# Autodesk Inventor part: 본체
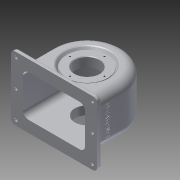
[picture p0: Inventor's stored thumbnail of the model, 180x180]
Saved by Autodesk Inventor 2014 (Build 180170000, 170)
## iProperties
Created: 2015-09
Part Number: 본체
Material: 알루미늄 6061
Document SubType Name: Modeling
Designer: SEC
Density: 2.71 g/cm^3
Appearance: 알루미늄 - 평지
Mass: 767.564 g
Surface Area: 941.03 cm^2
Volume: 283.234 cm^3
Author: SEC
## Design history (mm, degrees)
sketch "스케치1"
  geometry: L1 (-57, 0)-(-57, -47); L2 (57, 0)-(57, -47); L3 (57, -47)-(-57, -47); A1 r 57 centre (0, 0) between (57, 0) and (-57, 0); 1 further point
  constraints: 6 end point, 2 point on circle, 2 tangent, 1 centre point, 1 coincident, 1 parallel, 1 perpendicular, 1 vertical
  dimensions: "d1" = 47 distance from line of point (0, 0) L3; "d2" = 57 radius of A1
extrude "돌출1" new body sketch "스케치1" distance "d3" = 77; taper "d4" = 0 deg
sketch "스케치4"
  geometry: L1 (57, 77)-(57, 0) reference; L2 (57, 0)-(-47, 0) reference; L3 (-47, 77)-(57, 77) reference; L4 (-47, 0)-(-47, 77) reference; L5 (33, 73.111)-(33, 74); L6 (33, 74)-(20, 74); L7 (20, 74)-(20, 58); L8 (20, 58)-(28, 58); L9 (28, 58)-(39.747, 72); L10 (39.747, 72)-(51, 72); L11 (51, 72)-(51, 5); L12 (51, 5)-(20, 5); L13 (20, 5)-(20, 0); L14 (0, 0)-(0, 77); L15 (37.416, 77)-(0, 77); L16 (37.416, 77)-(33.883, 72.79); A1 r 0.5 centre (33.5, 73.111) between (33, 73.111) and (33.883, 72.79); 1 further point
  constraints: 24 end point, 7 perpendicular, 5 point on line, 2 parallel, 2 point on circle, 2 tangent, 1 centre point, 1 collinear
  dimensions: "d18" = 66 diameter of L5 L14; "d19" = 40 diameter of L7 L14; "d20" = 3 distance between parallel lines of L3 L6; "d21" = 50 deg angle of L8 L9; "d22" = 56 diameter of L8.end L14; "d23" = 16 distance between parallel lines of L8 L6; "d24" = 5 distance between parallel lines of L16 L9; "d25" = 6 distance between parallel lines of L11 L1; "d26" = 5 distance between parallel lines of L3 L10; "d27" = 5 distance between parallel lines of L12 L2; "d28" = 40 diameter of L13 L14; "d134" = 0.5 radius of A1
  node "절단 모서리 투영1"
sketch "스케치5"
  geometry: L1 (57, -47)-(-57, -47) reference; C1 r 31 at (0, 0)
  constraints: 1 centre point
  dimensions: "d29" = 62 diameter of C1; "d30" = 47 distance from line of C1.centre L1
extrude "돌출4" join sketch "스케치5" distance "d31" = 10; taper "d32" = 0 deg
sketch "스케치6"
  geometry: C1 r 31 at (0, 0) reference; C2 r 20 at (0, 0)
  constraints: 1 centre point, 1 coincident
  dimensions: "d34" = 40 diameter of C2
extrude "돌출5" cut sketch "스케치6" distance "d35" = 10; taper "d36" = 0 deg
sketch "스케치7"
  geometry: L1 (-13, 90.5)-(127, 90.5); L2 (127, 90.5)-(127, -13.5); L3 (127, -13.5)-(-13, -13.5); L4 (-13, -13.5)-(-13, 90.5); L5 (0, 0)-(0, 77) reference; L6 (0, 77)-(114, 77) reference; L7 (114, 77)-(114, 0) reference; L8 (114, 0)-(0, 0) reference; L9 (114, 38.5)-(80.915, 38.5); 1 further point
  constraints: 10 end point, 3 parallel, 1 horizontal, 1 midpoint, 1 perpendicular
  dimensions: "d37" = 140 distance of L1.start L1.end; "d38" = 104 distance of L1.end L2.end; "d39" = 70 distance from line of point (57, 0) L2; "d40" = 52 distance between parallel lines of L9 L1
extrude "돌출6" join sketch "스케치7" distance "d41" = 7; taper "d42" = 0 deg
revolve "회전2" stored, may be unused: angle "d43" = 90 deg
node "작업 평면1"
sketch "스케치14"
  geometry: L1 (29, 58)-(85, 58) reference; L2 (29, 58)-(17.253, 72) reference; L3 (85, 58)-(96.747, 72) reference; L4 (108, 72)-(108, 5) reference; L5 (6, 72)-(6, 5) reference; L6 (6, 5)-(108, 5) reference; L7 (6, 72)-(108, 72) reference; 1 further point
extrude "돌출10" cut sketch "스케치14" distance "d64" = 80; taper "d65" = 0 deg
sketch "스케치15"
  geometry: L1 (17.253, 72)-(29, 58) reference; L2 (29, 58)-(85, 58) reference; L3 (85, 58)-(96.747, 72) reference; L4 (127, -13.5)-(127, 90.5) reference; L5 (17.253, 72)-(96.747, 72); 1 further point
  constraints: 2 end point, 1 perpendicular, 1 point on line
extrude "돌출11" cut sketch "스케치15" distance "d67" = 15.5; taper "d68" = 0 deg
sketch "스케치18"
  geometry: L1 (-13, -90.5)-(127, -90.5) reference; L2 (-13, 13.5)-(-13, -90.5) reference; C1 r 2.5 at (-5, -82.5); C2 r 2.5 at (-5, -38.5); C3 r 2.5 at (-5, 5.5); 1 further point
  constraints: 3 centre point
  dimensions: "d69" = 5 diameter of C1; "d70" = 8 distance from line of C1.centre L1; "d71" = 8 distance from line of C1.centre L2; "d72" = 5 diameter of C2; "d73" = 5 diameter of C3; "d74" = 8 distance from line of C2.centre L2; "d75" = 8 distance from line of C3.centre L2; "d76" = 44 distance of C1.centre C2.centre; "d77" = 44 distance of C3.centre C2.centre
extrude "돌출12" cut sketch "스케치18" distance "d78" = 15.5; taper "d79" = 0 deg
node "작업 평면3"
sketch "스케치19"
  geometry: L1 (57, 0)-(57, 77) reference; L2 (57, 77)-(-57, 77) reference; C1 r 6 at (0, 38.5); 1 further point
  constraints: 1 centre point
  dimensions: "d81" = 12 diameter of C1; "d82" = 57 distance from line of C1.centre L1; "d83" = 38.5 distance from line of C1.centre L2
extrude "돌출13" join sketch "스케치19" stored distance "d84" = 15.5; taper "d85" = 10 deg
sketch "스케치20"
  geometry: C1 r 6 at (0, 0) reference; 1 further point
hole "구멍1" sketch "스케치20" at (0, 0) diameter "d86" = 4.459; stored, may be unused: countersink angle "d90" = 90 deg, drill point angle "d92" = 118 deg; dims "d87" = 20, "d88" = 4, "d89" = 2, "d91" = 25
sketch "스케치21"
  geometry: L1 (0, 57)-(0, 0) reference; L2 (90.5, -54)-(-13.5, -54) reference; 1 further point
  constraints: 1 other
  dimensions: "d93" = 38.5 distance from line of point (38.5, -24) L1; "d94" = 30 distance from line of point (38.5, -24) L2
feature "엠보싱1" sketch "스케치21" dims "d1" = 47, "d2" = 57, "d95" = 0.5, "d96" = 0
sketch "스케치22" dims "d97" = 56
  geometry: L1 (0, 0)-(0, 28); C1 r 20 at (0, 0) reference
  constraints: 2 end point, 1 coincident, 1 vertical, 1 vertical alignment, 2 other
hole "구멍2" sketch "스케치22" at (0, 28) diameter "d98" = 2.459; stored, may be unused: countersink angle "d102" = 90 deg, drill point angle "d104" = 118 deg; dims "d99" = 7, "d100" = 4, "d101" = 2, "d103" = 9
sketch "스케치23" dims "d108" = 48
  geometry: L1 (0, 0)-(0, 24); C1 r 31 at (0, 0) reference
  constraints: 2 end point, 1 coincident, 1 vertical, 1 vertical alignment, 2 other
hole "구멍3" sketch "스케치23" at (0, 24) diameter "d109" = 2.459; stored, may be unused: countersink angle "d113" = 90 deg, drill point angle "d115" = 118 deg; dims "d110" = 6, "d111" = 4, "d112" = 2, "d114" = 8
fillet "모깎기1" dims "d119" = 3
fillet "모깎기2" dims "d120" = 14
sketch "스케치24"
  geometry: L1 (6, 72)-(108, 72) reference; L2 (108, 72)-(108, 5) reference; L3 (108, 5)-(6, 5) reference; L4 (6.483, 72)-(6.483, 5) reference; L5 (107.517, 5)-(107.517, 72) reference; 1 further point
extrude "돌출14" join sketch "스케치24" distance "d121" = 60; taper "d122" = 0 deg
sketch "스케치25"
  geometry: L1 (6, 72)-(107.517, 72) reference; L2 (107.517, 5)-(6, 5) reference; L3 (6, 5)-(6, 72) reference; L4 (6.483, 72)-(6.483, 5) reference; 1 further point
extrude "돌출15" join sketch "스케치25" distance "d123" = 60; taper "d124" = 0 deg
fillet "모깎기3" dims "d125" = 9
fillet "모깎기4" dims "d126" = 9
fillet "모깎기5" dims "d127" = 9
fillet "모깎기6" dims "d128" = 7
fillet "모깎기7" dims "d129" = 3
chamfer "모따기1" distance "d130" = 1; stored, may be unused: second distance "d131" = 2, angle "d132" = 45 deg
fillet "모깎기8" dims "d133" = 1
node "솔리드1"
mirror "대칭1"
pattern_circular "원형 패턴1" dims angle "d106" = 360 deg
pattern_circular "원형 패턴2" dims angle "d117" = 360 deg
node "절단 모서리 투영2"
other parameters: "d0" = 114, "d63" = -47
